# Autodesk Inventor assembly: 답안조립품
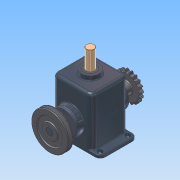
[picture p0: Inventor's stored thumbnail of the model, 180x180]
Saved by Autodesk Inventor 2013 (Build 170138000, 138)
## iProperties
Created: 2015-03
Part Number: 답안조립품
Document SubType Name: Assembly
Designer: Administrator
Mass: 8579.28 g
Surface Area: 4386.42 cm^2
Volume: 1982.54 cm^3
Density: 4.32742 g/cm^3
Author: Administrator
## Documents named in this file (15)
- C:\Documents and Settings\Administrator\바탕 화면\350305V1026\답안조립품.iam
- C:\Documents and Settings\Administrator\바탕 화면\350305V1026\본체.ipt
- C:\Documents and Settings\Administrator\바탕 화면\350305V1026\오일실.ipt
- C:\Documents and Settings\Administrator\바탕 화면\350305V1026\커버.ipt
- C:\Documents and Settings\Administrator\바탕 화면\350305V1026\베어링 6205.ipt
- C:\Documents and Settings\Administrator\바탕 화면\350305V1026\M4x0.5.ipt
- C:\Documents and Settings\Administrator\바탕 화면\350305V1026\편심축.ipt
- C:\Documents and Settings\Administrator\바탕 화면\350305V1026\키 8x8.ipt
- C:\Documents and Settings\Administrator\바탕 화면\350305V1026\멈춤링.ipt
- C:\Documents and Settings\Administrator\바탕 화면\350305V1026\V-벨트풀리.ipt
- C:\Documents and Settings\Administrator\바탕 화면\350305V1026\체인 스프로킷.ipt
- C:\Documents and Settings\Administrator\바탕 화면\350305V1026\부시.ipt
- C:\Documents and Settings\Administrator\바탕 화면\350305V1026\슬라이드.ipt
- C:\Documents and Settings\Administrator\바탕 화면\350305V1026\7 - 가변스프링.ipt
- C:\Documents and Settings\Administrator\바탕 화면\350305V1026\멈춤나사 M5x0.5.ipt
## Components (9 placed, 4 different names)
1. M4x0.5:1
2. M4x0.5:2
3. M4x0.5:3
4. M4x0.5:4
5. M4x0.5:5
6. M4x0.5:6
7. V-벨트풀리:1 — 플러쉬:1, 각도:3
8. 5-체인 스프로킷:1 — 플러쉬:2, 각도:4
9. 7 - 가변스프링:1
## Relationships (4: Flush 2, Angle 2)
- 플러쉬:1 [Flush]: V-벨트풀리:1
- 각도:3 [Angle]: V-벨트풀리:1
- 플러쉬:2 [Flush]: 5-체인 스프로킷:1
- 각도:4 [Angle]: 5-체인 스프로킷:1
